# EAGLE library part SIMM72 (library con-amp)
AMP connector
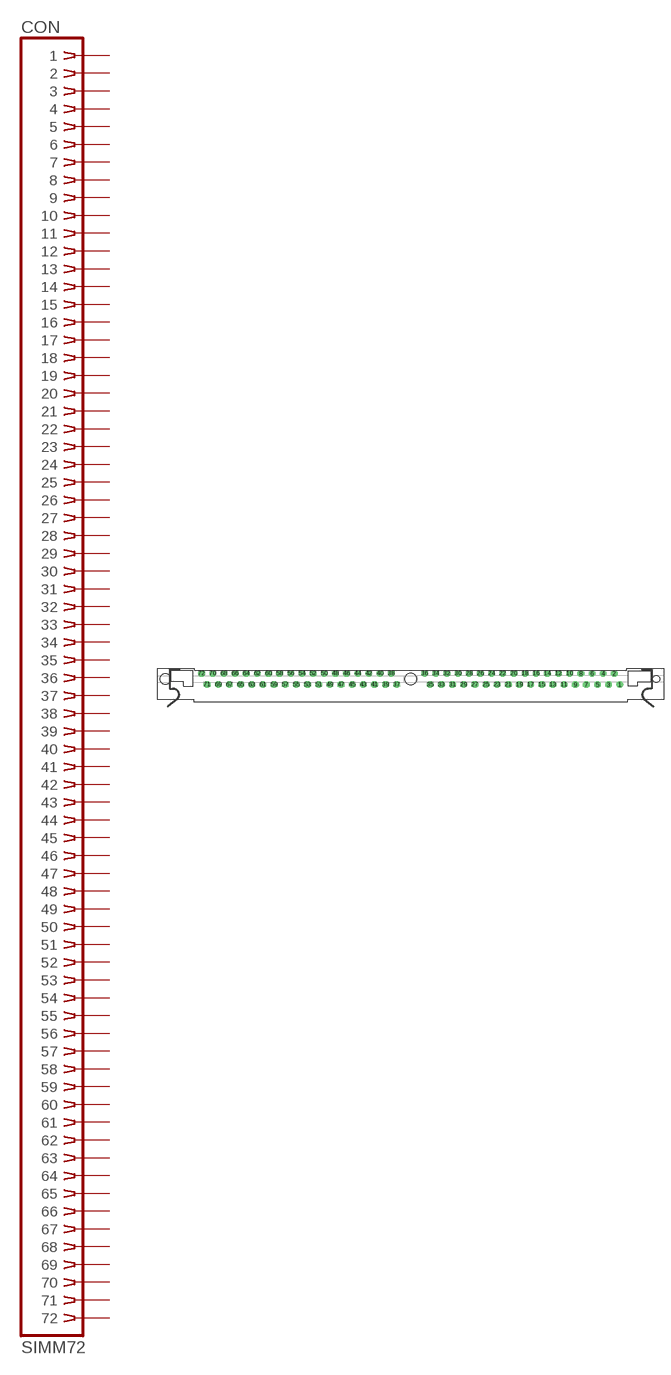
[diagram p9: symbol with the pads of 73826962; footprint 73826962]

Designator prefix CON

## SIMM72 (OC_FARNELL: unknown; OC_NEWARK: unknown)  [73826962]
1  1  pas
2  2  pas
3  3  pas
4  4  pas
5  5  pas
6  6  pas
7  7  pas
8  8  pas
9  9  pas
10  10  pas
11  11  pas
12  12  pas
13  13  pas
14  14  pas
15  15  pas
16  16  pas
17  17  pas
18  18  pas
19  19  pas
20  20  pas
21  21  pas
22  22  pas
23  23  pas
24  24  pas
25  25  pas
26  26  pas
27  27  pas
28  28  pas
29  29  pas
30  30  pas
31  31  pas
32  32  pas
33  33  pas
34  34  pas
35  35  pas
36  36  pas
37  37  pas
38  38  pas
39  39  pas
40  40  pas
41  41  pas
42  42  pas
43  43  pas
44  44  pas
45  45  pas
46  46  pas
47  47  pas
48  48  pas
49  49  pas
50  50  pas
51  51  pas
52  52  pas
53  53  pas
54  54  pas
55  55  pas
56  56  pas
57  57  pas
58  58  pas
59  59  pas
60  60  pas
61  61  pas
62  62  pas
63  63  pas
64  64  pas
65  65  pas
66  66  pas
67  67  pas
68  68  pas
69  69  pas
70  70  pas
71  71  pas
72  72  pas

## Footprint 73826962 (pad centres in mm)
SIMM II Socket
drill 1.016 round: 1 47.625,-1.27
drill 1.016 octagon: 2 46.355,1.27; 3 45.085,-1.27; 4 43.815,1.27; 5 42.545,-1.27; 6 41.275,1.27; 7 40.005,-1.27; 8 38.735,1.27; 9 37.465,-1.27; 10 36.195,1.27; 11 34.925,-1.27; 12 33.655,1.27; 13 32.385,-1.27; 14 31.115,1.27; 15 29.845,-1.27; 16 28.575,1.27; 17 27.305,-1.27; 18 26.035,1.27; 19 24.765,-1.27; 20 23.495,1.27; 21 22.225,-1.27; 22 20.955,1.27; 23 19.685,-1.27; 24 18.415,1.27; 25 17.145,-1.27; 26 15.875,1.27; 27 14.605,-1.27; 28 13.335,1.27; 29 12.065,-1.27; 30 10.795,1.27; 31 9.525,-1.27; 32 8.255,1.27; 33 6.985,-1.27; 34 5.715,1.27; 35 4.445,-1.27; 36 3.175,1.27; 37 -3.175,-1.27; 38 -4.445,1.27; 39 -5.715,-1.27; 40 -6.985,1.27; 41 -8.255,-1.27; 42 -9.525,1.27; 43 -10.795,-1.27; 44 -12.065,1.27; 45 -13.335,-1.27; 46 -14.605,1.27; 47 -15.875,-1.27; 48 -17.145,1.27; 49 -18.415,-1.27; 50 -19.685,1.27; 51 -20.955,-1.27; 52 -22.225,1.27; 53 -23.495,-1.27; 54 -24.765,1.27; 55 -26.035,-1.27; 56 -27.305,1.27; 57 -28.575,-1.27; 58 -29.845,1.27; 59 -31.115,-1.27; 60 -32.385,1.27; 61 -33.655,-1.27; 62 -34.925,1.27; 63 -36.195,-1.27; 64 -37.465,1.27; 65 -38.735,-1.27; 66 -40.005,1.27; 67 -41.275,-1.27; 68 -42.545,1.27; 69 -43.815,-1.27; 70 -45.085,1.27; 71 -46.355,-1.27; 72 -47.625,1.27
hole 2.362 at -55.88,0
hole 1.575 at 55.88,0
hole 2.54 at 0,0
